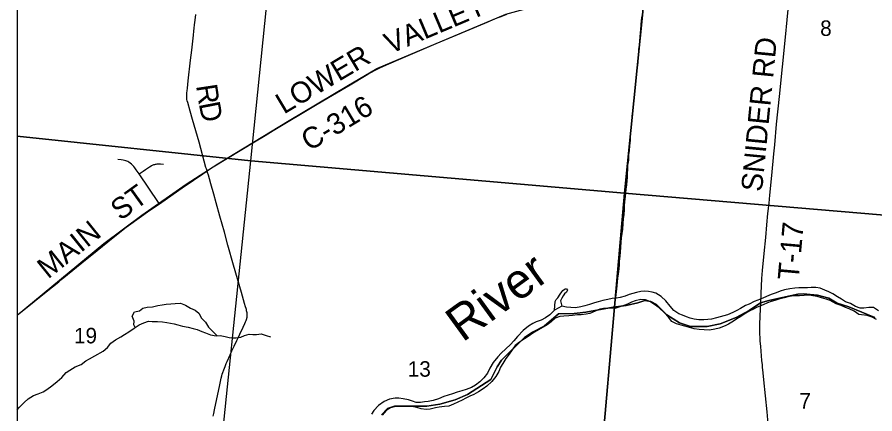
# Model space of a CAD drawing. Extents: x 831 to 1552, y 430 to 870.
# Drawn here: x 1250.77 to 1297.11, y 674.62 to 696.04 of the extents above; entities that cross this region are included whole.
import ezdxf

# ---------------------------------------------------------------- set-up
doc = ezdxf.new("R2010")
doc.units = 0
for name, color, linetype in [('GM_X_Corporation', 7, 'Continuous'), ('GM_X_County_Road', 7, 'Continuous'), ('GM_X_County_Road_Text', 7, 'Continuous'), ('GM_X_Major_River', 7, 'Continuous'), ('GM_X_Major_River_Text', 7, 'Continuous'), ('GM_X_Minor_River', 7, 'Continuous'), ('GM_X_Rail_Line', 7, 'Continuous'), ('GM_X_Section_Text', 7, 'Continuous'), ('GM_X_Township_Road', 7, 'Continuous'), ('GM_X_Township_Road_Text', 7, 'Continuous')]:
    doc.layers.add(name, color=color, linetype=linetype)

msp = doc.modelspace()

# ---------------------------------------------------------------- linework, layer by layer
at = {"layer": 'GM_X_Corporation'}
for points in [[(1250.766, 771.115), (1250.766, 667.013)], [(1297.111, 679.83), (1295.709, 680.4), (1295.073, 680.597), (1294.613, 680.86), (1294, 681.035), (1293.233, 681.1), (1292.948, 681.078), (1291.699, 680.815), (1291.373, 680.751), (1290.936, 680.613), (1290.319, 680.202), (1289.618, 679.83), (1288.742, 679.479), (1288.041, 679.347), (1287.142, 679.347), (1286.551, 679.545), (1285.871, 679.961), (1285.302, 680.53), (1284.995, 680.683), (1284.688, 680.749), (1284.294, 680.617), (1283.68, 680.464), (1282.974, 680.391), (1281.491, 680.106), (1280.857, 680.048), (1280.022, 680.019), (1279.244, 679.356), (1278.61, 679.039), (1278.178, 678.751), (1276.939, 677.512), (1276.708, 677.167), (1276.362, 676.475), (1275.095, 675.669), (1274.432, 675.38), (1273.596, 675.15), (1272.905, 675.035), (1271.147, 675.034), (1270.773, 674.919), (1270.456, 674.573)], [(1270.456, 674.573), (1270.773, 674.919), (1271.147, 675.034), (1272.905, 675.035), (1273.596, 675.15), (1274.432, 675.38), (1275.095, 675.669), (1276.362, 676.475), (1276.708, 677.167), (1276.939, 677.512), (1278.178, 678.751), (1278.61, 679.039), (1279.244, 679.356), (1280.022, 680.019), (1280.857, 680.048), (1281.491, 680.106), (1282.974, 680.391), (1283.68, 680.464), (1284.294, 680.617), (1284.688, 680.749), (1284.995, 680.683), (1285.302, 680.53), (1285.871, 679.961), (1286.551, 679.545), (1287.142, 679.347), (1288.041, 679.347), (1288.742, 679.479), (1289.618, 679.83), (1290.319, 680.202), (1290.936, 680.613), (1291.373, 680.751), (1291.699, 680.815), (1292.948, 681.078), (1293.233, 681.1), (1294, 681.035), (1294.613, 680.86), (1295.073, 680.597), (1295.709, 680.4), (1297.111, 679.83)]]:
    msp.add_lwpolyline(points, dxfattribs=at)
for points in [[(1250.766, 710.102), (1250.766, 689.618), (1263.383, 688.281), (1265.456, 708.606)], [(1265.456, 708.606), (1285.616, 706.68), (1283.584, 686.544), (1263.383, 688.281)], [(1305.299, 704.746), (1303.37, 684.858), (1283.584, 686.544), (1285.616, 706.68)], [(1250.766, 689.618), (1250.766, 669.354), (1261.315, 668.229), (1263.383, 688.281)], [(1263.383, 688.281), (1283.584, 686.544), (1281.807, 666.237), (1262.858, 668.098), (1261.315, 668.229)], [(1283.584, 686.544), (1303.37, 684.858), (1301.464, 664.502), (1281.807, 666.237)]]:
    msp.add_lwpolyline(points, close=True, dxfattribs=at)
at = {"layer": 'GM_X_County_Road'}
for points in [[(1261.024, 687.746), (1261.052, 687.764), (1261.356, 687.956), (1263.589, 689.303), (1264.173, 689.657), (1264.599, 689.912), (1266.889, 691.283), (1267.798, 691.821), (1268.765, 692.395), (1269.721, 692.957), (1270.11, 693.177), (1270.355, 693.302), (1270.714, 693.465), (1271.511, 693.812), (1273.397, 694.61), (1274.483, 695.072), (1276.029, 695.719), (1276.702, 695.999), (1276.91, 696.084), (1277.227, 696.204)], [(1258.453, 685.97), (1258.76, 686.182), (1259.677, 686.82), (1260.291, 687.24), (1260.802, 687.59), (1261.024, 687.746)], [(1250.766, 679.954), (1250.789, 679.971), (1251.13, 680.239), (1252.34, 681.209), (1253.013, 681.758), (1253.204, 681.916), (1253.492, 682.151), (1254.265, 682.775), (1254.795, 683.204), (1255.66, 683.909), (1256.581, 684.646), (1256.777, 684.798), (1257.943, 685.62), (1258.453, 685.97)]]:
    msp.add_lwpolyline(points, dxfattribs=at)
at = {"layer": 'GM_X_Major_River'}
msp.add_line((1280.189, 680.431), (1279.797, 680.227), dxfattribs=at)
for points in [[(1279.797, 680.227), (1279.83, 680.69), (1279.886, 680.795), (1279.979, 680.892), (1280.098, 681.079), (1280.199, 681.206), (1280.254, 681.274), (1280.324, 681.341), (1280.378, 681.37), (1280.454, 681.368), (1280.506, 681.291), (1280.442, 681.194), (1280.334, 681.097), (1280.263, 680.992), (1280.192, 680.872), (1280.16, 680.797), (1280.128, 680.729), (1280.189, 680.431)], [(1297.313, 680.178), (1297.028, 680.359), (1296.785, 680.364), (1296.518, 680.332), (1296.313, 680.329), (1296.064, 680.418), (1295.786, 680.576), (1295.529, 680.666), (1295.297, 680.815), (1295.094, 680.941), (1294.832, 681.099), (1294.629, 681.21), (1294.41, 681.306), (1294.161, 681.403), (1293.911, 681.439), (1293.668, 681.437), (1293.477, 681.433), (1293.241, 681.423), (1293.006, 681.421), (1292.777, 681.41), (1292.518, 681.378), (1292.22, 681.309), (1291.998, 681.245), (1291.767, 681.159), (1291.507, 681.058), (1291.246, 680.95), (1291.054, 680.87), (1290.785, 680.762), (1290.585, 680.683), (1290.316, 680.552), (1290.124, 680.465), (1289.847, 680.311), (1289.647, 680.201), (1289.431, 680.092), (1289.139, 679.969), (1288.557, 679.799), (1288.275, 679.737), (1288.076, 679.711), (1287.87, 679.692), (1287.604, 679.698), (1287.347, 679.742), (1287.127, 679.792), (1286.923, 679.858), (1286.713, 679.954), (1286.516, 680.026), (1286.247, 680.2), (1286.047, 680.44), (1285.809, 680.719), (1285.556, 680.96), (1285.279, 681.133), (1285.082, 681.199), (1284.885, 681.233), (1284.673, 681.238), (1284.459, 681.227), (1284.238, 681.179), (1284.031, 681.123), (1283.832, 681.059), (1283.625, 680.979), (1283.342, 680.902), (1283.151, 680.876), (1282.914, 680.85), (1282.685, 680.802), (1282.402, 680.74), (1282.157, 680.669), (1281.966, 680.613), (1281.682, 680.528), (1281.437, 680.457), (1281.223, 680.401), (1280.941, 680.354), (1280.69, 680.359), (1280.44, 680.387), (1280.189, 680.431)], [(1297.189, 679.724), (1296.971, 679.843), (1296.684, 679.933), (1296.244, 679.988), (1295.989, 680.161), (1295.719, 680.296), (1295.522, 680.369), (1295.296, 680.465), (1295.01, 680.571), (1294.686, 680.737), (1294.475, 680.81), (1294.226, 680.884), (1293.984, 680.95), (1293.764, 681.001), (1293.552, 681.021), (1293.285, 681.004), (1293.042, 681.002), (1292.814, 680.999), (1292.608, 680.981), (1292.409, 680.932), (1292.202, 680.883), (1291.927, 680.821), (1291.705, 680.749), (1291.498, 680.685), (1291.307, 680.621), (1291.068, 680.512), (1290.754, 680.382), (1290.553, 680.28), (1290.354, 680.193), (1290.145, 680.061), (1289.867, 679.877), (1289.659, 679.745), (1289.466, 679.619), (1289.204, 679.473), (1289.012, 679.371), (1288.697, 679.256), (1288.46, 679.193), (1288.177, 679.138), (1287.889, 679.152), (1287.623, 679.173), (1287.343, 679.217), (1287.085, 679.276), (1286.843, 679.35), (1286.647, 679.415), (1286.39, 679.481), (1286.134, 679.616), (1285.957, 679.848), (1285.734, 680.081), (1285.451, 680.346), (1285.197, 680.534), (1284.942, 680.692), (1284.715, 680.773), (1284.457, 680.794), (1284.159, 680.717), (1283.96, 680.653), (1283.752, 680.551), (1283.545, 680.464), (1283.338, 680.4), (1283.116, 680.336), (1282.91, 680.326), (1282.674, 680.308), (1282.446, 680.305), (1282.247, 680.279), (1281.994, 680.171)], [(1279.797, 680.227), (1279.548, 679.966), (1279.308, 679.804), (1279.07, 679.687), (1278.817, 679.586), (1278.624, 679.492), (1278.393, 679.352), (1278.106, 679.123), (1277.802, 678.802), (1277.607, 678.571), (1277.42, 678.369), (1277.164, 678.124), (1276.923, 677.901), (1276.736, 677.7), (1276.478, 677.401), (1276.304, 677.093), (1276.183, 676.822), (1275.972, 676.561), (1275.762, 676.345), (1275.537, 676.175), (1275.307, 676.05), (1275.03, 675.942), (1274.8, 675.864), (1274.54, 675.786), (1274.287, 675.708), (1273.827, 675.55), (1273.528, 675.428), (1273.244, 675.335), (1272.977, 675.287), (1272.771, 675.262), (1272.558, 675.243), (1272.329, 675.241), (1272.133, 675.306), (1271.906, 675.372), (1271.619, 675.439), (1271.391, 675.467), (1271.186, 675.464), (1270.888, 675.417), (1270.589, 675.286), (1270.287, 675.072), (1270.038, 674.804), (1269.911, 674.602)], [(1281.994, 680.171), (1281.71, 680.04), (1281.519, 680.006), (1281.244, 679.974), (1281.046, 679.963), (1280.764, 679.939), (1280.566, 679.921), (1280.299, 679.904), (1280.094, 679.885), (1279.833, 679.785), (1279.623, 679.591), (1279.406, 679.436), (1279.19, 679.297), (1278.928, 679.15), (1278.628, 678.982), (1278.435, 678.842), (1278.172, 678.68), (1277.917, 678.495), (1277.67, 678.318), (1277.513, 678.086), (1277.355, 677.838), (1277.167, 677.607), (1277.009, 677.344), (1276.883, 677.149), (1276.786, 676.915), (1276.628, 676.645), (1276.409, 676.376), (1276.137, 676.116), (1275.944, 675.968), (1275.689, 675.814), (1275.442, 675.667), (1275.22, 675.573), (1275.012, 675.464), (1274.812, 675.369), (1274.335, 675.151), (1274.082, 675.043), (1273.853, 675.01), (1273.563, 674.978), (1273.372, 674.944), (1273.074, 674.882), (1272.861, 674.849), (1272.603, 674.893), (1272.369, 674.959), (1272.088, 675.01), (1271.815, 675.039), (1271.625, 675.043), (1271.374, 675.033), (1271.137, 674.993), (1270.946, 674.944), (1270.699, 674.805), (1270.481, 674.543)]]:
    msp.add_lwpolyline(points, dxfattribs=at)
at = {"layer": 'GM_X_Minor_River'}
for points in [[(1283.108, 680.871), (1283.126, 681.077), (1283.167, 681.35), (1283.185, 681.554), (1283.22, 681.949), (1283.253, 682.161), (1283.287, 682.449), (1283.313, 682.677), (1283.315, 682.874), (1283.341, 683.14), (1283.359, 683.344), (1283.385, 683.625), (1283.396, 683.898), (1283.422, 684.118), (1283.462, 684.353), (1283.488, 684.58), (1283.515, 684.899), (1283.533, 685.172), (1283.559, 685.369), (1283.577, 685.665), (1283.58, 685.87), (1283.598, 686.067), (1283.631, 686.356), (1283.649, 686.56), (1283.667, 686.75), (1283.708, 686.985), (1283.718, 687.205), (1283.735, 687.395), (1283.745, 687.592), (1283.756, 687.82), (1283.766, 688.047), (1283.808, 688.328), (1283.819, 688.601), (1283.844, 688.844), (1283.878, 689.094), (1283.897, 689.382), (1283.907, 689.572), (1283.917, 689.815), (1283.935, 690.042), (1283.961, 690.262), (1283.994, 690.505), (1284.004, 690.71), (1284.03, 690.929), (1284.047, 691.134), (1284.088, 691.354), (1284.106, 691.559), (1284.116, 691.771), (1284.183, 692.256), (1284.193, 692.492), (1284.211, 692.681), (1284.229, 692.962), (1284.28, 693.341), (1284.313, 693.584), (1284.323, 693.796), (1284.349, 694.054), (1284.36, 694.289), (1284.385, 694.524), (1284.403, 694.752), (1284.421, 694.972), (1284.439, 695.177), (1284.464, 695.374), (1284.49, 695.632), (1284.508, 695.852), (1284.534, 696.11)], [(1257.138, 679.293), (1257.078, 679.431), (1257.088, 679.628), (1256.978, 679.888), (1257.11, 680.129), (1257.369, 680.179), (1257.56, 680.329), (1257.789, 680.379), (1258.078, 680.406), (1258.367, 680.471), (1258.603, 680.514), (1258.817, 680.542), (1259.075, 680.554), (1259.303, 680.582), (1259.592, 680.601), (1259.857, 680.492), (1260.128, 680.321), (1260.385, 680.212), (1260.581, 680.058), (1260.722, 679.791), (1260.939, 679.568), (1261.111, 679.308), (1261.57, 678.843)], [(1255.409, 678.005), (1255.65, 678.202), (1255.835, 678.443), (1256.081, 678.615), (1256.364, 678.779), (1256.563, 678.913), (1256.793, 679.047), (1257.084, 679.256), (1257.352, 679.435), (1257.604, 679.539), (1257.856, 679.627), (1258.068, 679.609), (1258.357, 679.613), (1258.623, 679.595), (1258.85, 679.547), (1259.047, 679.514), (1259.244, 679.481), (1259.441, 679.434), (1259.706, 679.354), (1260.002, 679.298), (1260.282, 679.226), (1260.494, 679.171), (1260.743, 679.077), (1260.94, 678.998), (1261.204, 678.897), (1261.515, 678.84), (1261.736, 678.852), (1262.001, 678.796), (1262.213, 678.748), (1262.403, 678.723), (1262.608, 678.728), (1262.852, 678.771), (1263.042, 678.845), (1263.294, 678.925), (1263.499, 678.908), (1263.704, 678.905), (1263.955, 678.94), (1264.212, 678.846), (1264.455, 678.783)], [(1250.766, 674.845), (1250.89, 674.991), (1251.151, 675.238), (1251.358, 675.44), (1251.641, 675.611), (1251.907, 675.699), (1252.174, 675.809), (1252.365, 675.936), (1252.633, 676.13), (1252.924, 676.377), (1253.177, 676.579), (1253.416, 676.857), (1253.607, 676.983), (1253.905, 677.154), (1254.233, 677.294), (1254.485, 677.481), (1254.684, 677.592), (1254.967, 677.763), (1255.409, 678.005)]]:
    msp.add_lwpolyline(points, dxfattribs=at)
at = {"layer": 'GM_X_Rail_Line'}
msp.add_lwpolyline([(1250.766, 679.957), (1255.444, 683.813), (1257.495, 685.358), (1259.895, 687.02), (1261.608, 688.118), (1265.466, 690.461), (1268.571, 692.318), (1270.198, 693.26), (1277.176, 696.209), (1284.864, 698.305), (1290.582, 698.552), (1291.934, 698.299), (1293.404, 698.016), (1295.482, 697.897), (1297.508, 698.271), (1299.512, 698.644), (1302.371, 699.157), (1309.027, 700.546), (1335.38, 705.567), (1347.114, 707.619), (1348.184, 707.837)], dxfattribs=at)
at = {"layer": 'GM_X_Township_Road'}
for points in [[(1290.94, 680.602), (1290.959, 681.116), (1291.008, 681.922), (1291.041, 682.355), (1291.127, 683.282), (1291.209, 684.147), (1291.272, 684.828), (1291.334, 685.445), (1291.393, 686.001), (1291.437, 686.433), (1291.548, 687.483), (1291.653, 688.658), (1291.699, 689.153), (1291.802, 690.266), (1291.952, 691.749), (1292.277, 694.962), (1292.37, 695.889), (1292.462, 696.816), (1292.555, 697.805), (1292.607, 698.423), (1292.633, 698.634)], [(1261.024, 687.746), (1260.994, 687.844), (1260.968, 687.931), (1260.595, 689.284), (1260.247, 690.512), (1260.111, 690.966), (1259.98, 691.432), (1259.955, 691.519), (1259.943, 691.593), (1259.934, 691.65), (1259.928, 691.723), (1259.927, 691.795), (1259.931, 691.877), (1259.935, 691.954), (1259.946, 692.062), (1259.963, 692.213), (1260.012, 692.598), (1260.134, 693.711), (1260.199, 694.266), (1260.251, 694.737), (1260.286, 695.077), (1260.307, 695.282), (1260.327, 695.442), (1260.35, 695.625), (1260.381, 695.879), (1260.416, 696.178)], [(1257.354, 687.574), (1257.19, 687.806), (1257.126, 687.901), (1257.066, 687.98), (1257.015, 688.038), (1256.947, 688.104), (1256.874, 688.161), (1256.799, 688.211), (1256.745, 688.241), (1256.69, 688.265), (1256.635, 688.286), (1256.575, 688.304), (1256.486, 688.323), (1256.394, 688.337), (1256.209, 688.354)], [(1257.354, 687.574), (1257.573, 687.732), (1257.704, 687.824), (1257.803, 687.894), (1257.858, 687.929), (1257.909, 687.961), (1257.949, 687.985), (1258.02, 688.026), (1258.081, 688.054), (1258.116, 688.068), (1258.158, 688.083), (1258.198, 688.094), (1258.234, 688.102), (1258.281, 688.11), (1258.335, 688.117), (1258.385, 688.12), (1258.446, 688.12), (1258.512, 688.117), (1258.677, 688.107)], [(1261.355, 674.498), (1261.387, 674.64), (1261.43, 674.835), (1261.713, 676.194), (1261.788, 676.548), (1261.82, 676.67), (1261.847, 676.763), (1261.881, 676.863), (1261.928, 677.003), (1261.997, 677.176), (1262.068, 677.343), (1262.119, 677.453), (1262.277, 677.809), (1262.373, 678.022), (1262.424, 678.13), (1262.491, 678.274), (1262.631, 678.574), (1262.673, 678.66), (1262.719, 678.758), (1262.806, 678.933), (1262.979, 679.302), (1263.067, 679.496), (1263.106, 679.586), (1263.135, 679.654), (1263.161, 679.725), (1263.174, 679.774), (1263.18, 679.8), (1263.186, 679.832), (1263.189, 679.855), (1263.191, 679.884), (1263.195, 679.946), (1263.193, 679.991), (1263.185, 680.07), (1263.176, 680.128), (1263.163, 680.192), (1263.15, 680.249), (1263.133, 680.313), (1263.11, 680.393), (1263.056, 680.574), (1262.887, 681.168), (1262.45, 682.645), (1262.155, 683.737), (1261.967, 684.433), (1261.85, 684.856), (1261.725, 685.301), (1261.524, 686.018), (1261.394, 686.483), (1261.239, 687.034), (1261.158, 687.304), (1261.098, 687.503), (1261.052, 687.653), (1261.024, 687.746)], [(1258.453, 685.97), (1258.404, 686.041), (1257.354, 687.574)], [(1291.473, 672.73), (1291.415, 673.379), (1291.325, 674.304), (1291.281, 674.736), (1291.193, 675.599), (1291.113, 676.463), (1291.076, 676.833), (1291.046, 677.141), (1291.034, 677.264), (1291.01, 677.511), (1290.962, 678.003), (1290.94, 678.25), (1290.915, 678.559), (1290.903, 678.744), (1290.893, 678.93), (1290.888, 679.116), (1290.89, 679.426), (1290.908, 679.921), (1290.94, 680.602)]]:
    msp.add_lwpolyline(points, dxfattribs=at)

# ---------------------------------------------------------------- texts
at = {"layer": 'GM_X_County_Road_Text'}
for s, rotation, p in [('VALLEY', 22.8831, (1270.911, 694.036)), ('LOWER', 30.798, (1265.175, 690.776)), ('C-316', 30.8702, (1266.548, 688.779)), ('ST', 35.8113, (1256.342, 685.021)), ('MAIN', 38.8907, (1252.437, 681.871))]:
    msp.add_text(s, height=1.1364, rotation=rotation, dxfattribs=at).set_placement(p)
at = {"layer": 'GM_X_Major_River_Text'}
msp.add_text('River', height=1.8937, rotation=35.998, dxfattribs=at).set_placement((1274.829, 678.455))
at = {"layer": 'GM_X_Section_Text'}
for s, height, p in [('8', 0.837, (1294.154, 695.027)), ('19', 0.8371, (1253.837, 678.427)), ('13', 0.8371, (1271.871, 676.627)), ('7', 0.837, (1293.029, 674.904))]:
    msp.add_text(s, height=height, rotation=0, dxfattribs=at).set_placement(p)
at = {"layer": 'GM_X_Township_Road_Text'}
for s, height, rotation, p in [('SNIDER RD', 1.1364, 84.4057, (1291.009, 686.584)), ('R', 1.136, 278.6586, (1260.43, 692.342)), ('D', 1.136, 280.8899, (1260.578, 691.372)), ('T-17', 1.1364, 84.8436, (1292.986, 681.807))]:
    msp.add_text(s, height=height, rotation=rotation, dxfattribs=at).set_placement(p)

doc.saveas('drawing.dxf')
